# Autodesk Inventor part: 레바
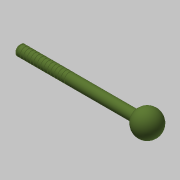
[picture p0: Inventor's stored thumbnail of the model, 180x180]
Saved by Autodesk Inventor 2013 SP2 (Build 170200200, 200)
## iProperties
Created: 2015-12
Part Number: 레바
Material: 스테인리스강
Document SubType Name: Modeling
Designer: mduedu
Density: 8.08 g/cm^3
Mass: 30.6794 g
Surface Area: 23.0487 cm^2
Volume: 3.79696 cm^3
Author: mduedu
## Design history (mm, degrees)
sketch "스케치1"
  geometry: C1 r 3 at (0, 0); 1 further point
  constraints: 1 centre point, 1 coincident
  dimensions: "d0" = 6 diameter of C1
extrude "돌출1" new body sketch "스케치1" distance "d1" = 75; taper "d2" = 0 deg
sketch "스케치2"
  geometry: L1 (7.5, 0)-(-6, 0); L2 (-6, 4.5)-(-6, 0); A1 r 7.5 centre (0, 0) between (7.5, 0) and (-6, 4.5); 2 further points
  constraints: 4 end point, 2 coincident, 2 point on circle, 1 centre point, 1 horizontal, 1 perpendicular, 1 point on line
  dimensions: "d3" = 15 diameter of A1; "d10" = 6 distance from line of L2 point (0, 0)
revolve "회전1" sketch "스케치2" stored, may be unused: angle "d4" = 90 deg
chamfer "모따기1" distance "d7" = 0.5; stored, may be unused: second distance "d8" = 2, angle "d9" = 45 deg
fillet "모깎기2" dims "d11" = 0.3
sketch "스케치4"
  geometry: L1 (-75, -2.5)-(-75, 2.5) reference; L2 (-75, 0)-(0, 0); L3 (-6.3, 3)-(-74.5, 3) reference; L4 (-74, 3)-(-73.9, 3); L5 (-73.9, 3)-(-73.9, 2.9); L6 (-73.9, 2.9)-(-74, 2.9); L7 (-74, 2.9)-(-74, 3)
  constraints: 10 end point, 2 parallel, 2 perpendicular, 1 horizontal, 1 midpoint, 1 point on line
  dimensions: "d17" = 1 distance between parallel lines of L7 L1; "d18" = 0.1 distance of L5.end L6.end; "d19" = 0.1 distance of L4.end L5.end
revolve "회전3" sketch "스케치4" stored, may be unused: angle "d20" = 90 deg
node "솔리드1"
pattern_linear "직사각형 패턴1" dims "d23" = 2
